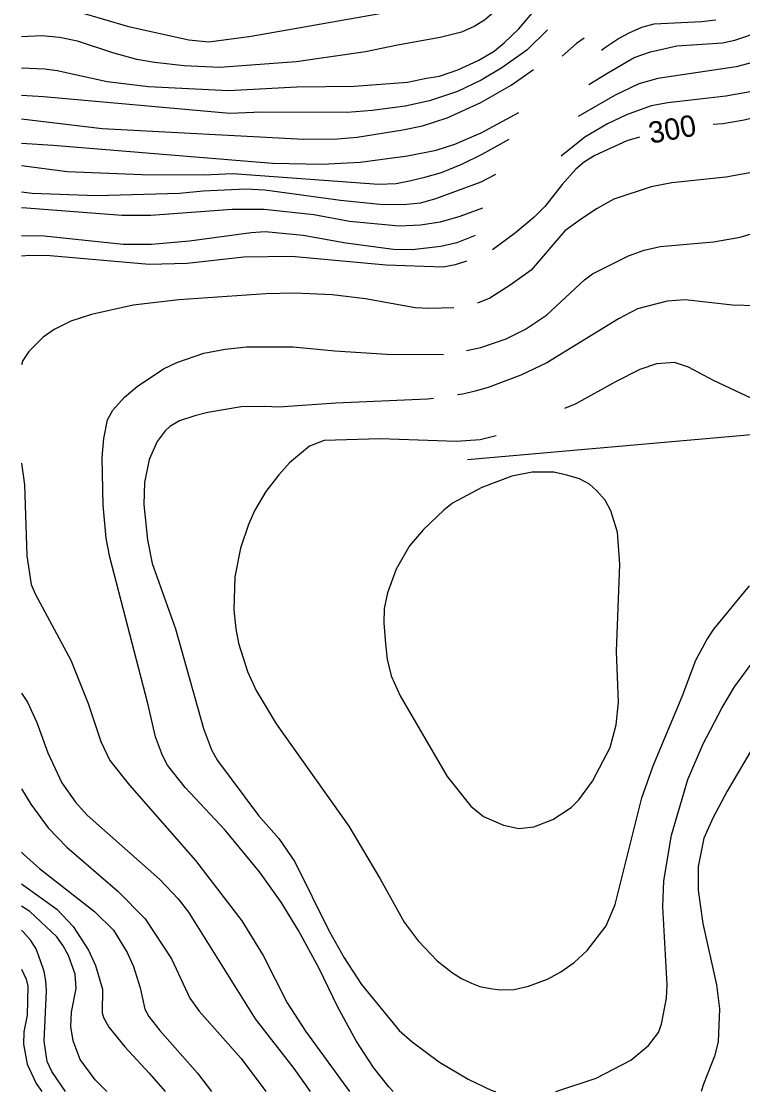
# Model space of a CAD drawing. Extents: x -555860 to -552701, y -1187050 to -1182291.
# Drawn here: x -555860 to -555523, y -1187050 to -1186550 of the extents above; entities that cross this region are included whole.
import ezdxf

# ---------------------------------------------------------------- set-up
doc = ezdxf.new("R2010")
doc.units = 0
for name, color, linetype in [('Level 28', 7, 'Continuous'), ('Level 40', 7, 'Continuous'), ('Level 41', 7, 'Continuous')]:
    doc.layers.add(name, color=color, linetype=linetype)

msp = doc.modelspace()

# ---------------------------------------------------------------- linework, layer by layer
at = {"layer": 'Level 28'}
msp.add_lwpolyline([(-555508.02, -1186742.24), (-555651.46, -1186754.81)], dxfattribs=at)
at = {"layer": 'Level 40'}
for points in [[(-555860.13, -1186544.05), (-555858.07, -1186543.84), (-555842.82, -1186543.42), (-555833.39, -1186545.22), (-555810.09, -1186552.02), (-555781.81, -1186558.26), (-555772.38, -1186559.23), (-555752.69, -1186556.59), (-555687.21, -1186544.99), (-555675.87, -1186541.34), (-555659.23, -1186538.01), (-555653.69, -1186536.21), (-555643.98, -1186531.22), (-555635.66, -1186525.4), (-555632.06, -1186521.65), (-555608.21, -1186491.01), (-555601.55, -1186483.94), (-555594.19, -1186479.33), (-555587.69, -1186476.59), (-555567.15, -1186470.24)], [(-555430.17, -1186544.81), (-555482.03, -1186578.36), (-555506.99, -1186591.4), (-555511.98, -1186593.34), (-555521.96, -1186595.83), (-555531.95, -1186597.5), (-555536.57, -1186597.92)], [(-555596.95, -1186557.53), (-555600.51, -1186559.99), (-555607.24, -1186565.88)], [(-555860.13, -1186606.69), (-555845.31, -1186607.62), (-555742.7, -1186615.94), (-555719.41, -1186616.49), (-555701.66, -1186615.52), (-555679.48, -1186612.61), (-555666.17, -1186609.84), (-555657.43, -1186607.06), (-555645.09, -1186601.8), (-555627.48, -1186592.23)], [(-555571, -1186603.8), (-555576.87, -1186605.54), (-555591.85, -1186612.33), (-555596.7, -1186615.38), (-555600.72, -1186618.85), (-555607.24, -1186625.92), (-555615.14, -1186636.04), (-555620.27, -1186641.31), (-555629.01, -1186648.52), (-555639.79, -1186656.58)], [(-555651.92, -1186661.77), (-555657.29, -1186663.61), (-555662.84, -1186664.61), (-555689.46, -1186663.78), (-555733.83, -1186659.62), (-555756.02, -1186660.03), (-555782.64, -1186662.94), (-555800.39, -1186663.36), (-555846.7, -1186659.34), (-555856.13, -1186659.2), (-555860.13, -1186659.55)], [(-555689.88, -1186840.84), (-555688.96, -1186848.14), (-555687.1, -1186855.82), (-555682.94, -1186865.24), (-555660.9, -1186902.96), (-555649.94, -1186916.82), (-555643.98, -1186921.68), (-555634.55, -1186925.7), (-555627.39, -1186927.4), (-555620.49, -1186926.6), (-555611.54, -1186923.06), (-555602.94, -1186917.52), (-555599.33, -1186913.91), (-555592.95, -1186905.18), (-555584.64, -1186889.37), (-555581.86, -1186878.83), (-555580.75, -1186868.29), (-555581.72, -1186844.45), (-555580.2, -1186803.68), (-555581.31, -1186788.71), (-555584.36, -1186778.72), (-555587.13, -1186773.73), (-555590.88, -1186769.29), (-555594.34, -1186766.24), (-555599.1, -1186763.74), (-555604.98, -1186762.04), (-555611.09, -1186760.64), (-555621.24, -1186760.56), (-555630.67, -1186762.5), (-555644.81, -1186767.77), (-555658.4, -1186775.12), (-555662.56, -1186778.31), (-555671.99, -1186787.46), (-555678.65, -1186795.08), (-555684.88, -1186805.9), (-555688.91, -1186816.99), (-555690.45, -1186824.38), (-555690.57, -1186831.13), (-555689.88, -1186840.84)], [(-555860.13, -1186864.04), (-555857.23, -1186868.29), (-555852.94, -1186877.72), (-555847.81, -1186891.87), (-555841.15, -1186906.01), (-555834.77, -1186915.02), (-555829.36, -1186921.12), (-555795.39, -1186951.21), (-555786.8, -1186960.22), (-555781.95, -1186966.46), (-555750.75, -1187016.38), (-555732.72, -1187039.68), (-555725.07, -1187050.46)], [(-555839.57, -1187050.46), (-555845.86, -1187041.06), (-555848.08, -1187036.35), (-555849.47, -1187026.92), (-555848.36, -1187003.35), (-555848.64, -1186998.63), (-555849.54, -1186994.31), (-555851.13, -1186989.2), (-555853.25, -1186983.66), (-555855.71, -1186979.77), (-555859.39, -1186975.5), (-555860.13, -1186974.92)]]:
    msp.add_lwpolyline(points, dxfattribs=at)
at = {"layer": 'Level 41'}
for points in [[(-555594.65, -1186579.2), (-555585.5, -1186573.52), (-555573.54, -1186566.58), (-555565.78, -1186563.8), (-555553.58, -1186561.03), (-555532.22, -1186559.64), (-555526.39, -1186558.42), (-555520.3, -1186556.32), (-555514.75, -1186553.82), (-555505.88, -1186547.58), (-555499.64, -1186542.03), (-555478.15, -1186520.68), (-555466.08, -1186511.67), (-555457.35, -1186508.06), (-555451.25, -1186506.4), (-555430.73, -1186503.76), (-555422.94, -1186502.1), (-555416.58, -1186500.16), (-555410.76, -1186497.25), (-555397.17, -1186487.68), (-555379.15, -1186472.29), (-555345.18, -1186434.71)], [(-555573.34, -1186489.11), (-555582.97, -1186491.43), (-555591.29, -1186494.75), (-555595.43, -1186497.15), (-555599.61, -1186499.88), (-555607.24, -1186507.51), (-555632.75, -1186539.82), (-555643.57, -1186549.11), (-555648.38, -1186551.98), (-555654.24, -1186554.65), (-555664.22, -1186557.15), (-555684.19, -1186560.75), (-555699.17, -1186563.94), (-555731.61, -1186568.52), (-555767.39, -1186571.15), (-555784.03, -1186570.46), (-555797.89, -1186568.93), (-555806.21, -1186567.41), (-555817.3, -1186564.36), (-555833.94, -1186558.81), (-555842.26, -1186557.15), (-555850.58, -1186556.45), (-555860.13, -1186556.79)], [(-555860.13, -1186571.37), (-555849.19, -1186571.84), (-555843.37, -1186572.68), (-555820.07, -1186577.81), (-555800.66, -1186580.03), (-555763.23, -1186581.97), (-555731.33, -1186580.3), (-555704.44, -1186579.89), (-555679.48, -1186578.09), (-555670.66, -1186576.24), (-555664.5, -1186575.31), (-555656.05, -1186572.28), (-555646.48, -1186567.96), (-555638.97, -1186563.62), (-555634.28, -1186559.64), (-555627.48, -1186553.13), (-555621.93, -1186546.75), (-555600.17, -1186517.63), (-555596.01, -1186513.89), (-555589.63, -1186509.73), (-555578.91, -1186504.86)], [(-555462.62, -1186527.34), (-555492.98, -1186554.38), (-555508.38, -1186564.64), (-555512.78, -1186566.84), (-555518.08, -1186568.8), (-555525.84, -1186570.88), (-555562.45, -1186576.42), (-555571.32, -1186578.92), (-555582.42, -1186584.19), (-555599.64, -1186594.08)], [(-555376.1, -1186543.14), (-555395.09, -1186555.76), (-555421.85, -1186571.29), (-555447.92, -1186584.88), (-555469.97, -1186600.41), (-555480.92, -1186607.34), (-555489.79, -1186612.19), (-555501.44, -1186616.22), (-555515.03, -1186619.68), (-555530.56, -1186622.46), (-555555.8, -1186625.23), (-555565.5, -1186627.03), (-555582.97, -1186632.85), (-555590.74, -1186637.15), (-555598.13, -1186642.08), (-555605.99, -1186647.69), (-555621.66, -1186665.99), (-555631.55, -1186673.02), (-555640.93, -1186679.17), (-555646.83, -1186681.53)], [(-555455.96, -1186541.76), (-555483.14, -1186565.61), (-555495.9, -1186574.76), (-555502.55, -1186578.22), (-555509.06, -1186580.45), (-555519.19, -1186582.66), (-555530.56, -1186584.6), (-555557.74, -1186587.79), (-555565.5, -1186589.18), (-555577.15, -1186593.34), (-555586, -1186597.53), (-555596.56, -1186603.74), (-555607.65, -1186612.68)], [(-555614.1, -1186553.61), (-555623.62, -1186563.12), (-555635.38, -1186571.43), (-555645.09, -1186577.11), (-555656.18, -1186582.38), (-555669.17, -1186586.88), (-555680.56, -1186589.36), (-555696.12, -1186591.4), (-555707.76, -1186592.23), (-555747.7, -1186592.09), (-555762.67, -1186592.78), (-555849.75, -1186584.88), (-555860.13, -1186584.26)], [(-555588.7, -1186563.04), (-555587.41, -1186562), (-555580.89, -1186557.56), (-555575.85, -1186554.96), (-555569.94, -1186552.3), (-555564.11, -1186550.77), (-555541.93, -1186549.66), (-555535.27, -1186548.83)], [(-555860.13, -1186595.17), (-555822.29, -1186599.72), (-555728.01, -1186604.71), (-555712.2, -1186604.57), (-555703.05, -1186603.74), (-555681.7, -1186600.41), (-555672.54, -1186598.47), (-555660.9, -1186594.72), (-555645.23, -1186587.65), (-555631.09, -1186579.47), (-555620.63, -1186572.07)], [(-555860.13, -1186617.08), (-555838.66, -1186619.82), (-555803.71, -1186621.21), (-555774.6, -1186621.49), (-555761.29, -1186620.79), (-555693.07, -1186625.78), (-555684.77, -1186625.5), (-555678.65, -1186624.26), (-555671.4, -1186622.53), (-555663.67, -1186620.38), (-555654.1, -1186616.49), (-555644.54, -1186611.78), (-555632, -1186604.71)], [(-555638.34, -1186621.31), (-555645.25, -1186624.93), (-555666.44, -1186632.72), (-555673.38, -1186634.65), (-555679.76, -1186635.35), (-555690.85, -1186635.49), (-555710.81, -1186633.41), (-555746.31, -1186628.56), (-555755.18, -1186628.14), (-555775.15, -1186629.11), (-555786.24, -1186630.22), (-555825.07, -1186631.19), (-555855.02, -1186630.22), (-555860.13, -1186629.54)], [(-555644.38, -1186637.08), (-555655.07, -1186640.9), (-555664.22, -1186643.56), (-555673.38, -1186644.92), (-555683.36, -1186645.47), (-555706.65, -1186643.25), (-555723.29, -1186640.2), (-555746.59, -1186637.71), (-555761.56, -1186637.71), (-555799.55, -1186640.48), (-555813.14, -1186640.48), (-555857.79, -1186637.01), (-555860.13, -1186636.9)], [(-555647.81, -1186649.86), (-555656.47, -1186653.26), (-555663.95, -1186655.04), (-555677.26, -1186656.57), (-555686.13, -1186656.43), (-555708.32, -1186653.38), (-555728.29, -1186649.77), (-555746.03, -1186648.11), (-555752.69, -1186648.52), (-555781.53, -1186652.54), (-555799.28, -1186654.07), (-555812.59, -1186654.07), (-555849.47, -1186650.19), (-555860.13, -1186650.01)], [(-555651.85, -1186703.66), (-555645.16, -1186702.22), (-555633.44, -1186698.16), (-555624.29, -1186693.59), (-555614.45, -1186687.07), (-555596.7, -1186670.57), (-555592.95, -1186667.8), (-555576.18, -1186659.34), (-555568.83, -1186656.7), (-555561.34, -1186654.9), (-555536.38, -1186652.82), (-555523.9, -1186650.6), (-555508.93, -1186646.03)], [(-555657.87, -1186683.62), (-555669.49, -1186684.06), (-555675.87, -1186683.6), (-555699.17, -1186679.44), (-555714.7, -1186677.64), (-555732.17, -1186676.81), (-555745.76, -1186677.09), (-555786.52, -1186679.86), (-555807.87, -1186682.49), (-555827.29, -1186686.79), (-555836.99, -1186689.98), (-555844.76, -1186693.86), (-555849.89, -1186697.47), (-555856.68, -1186704.12), (-555859.45, -1186708.28), (-555860.13, -1186710.38)], [(-555516.42, -1186682.77), (-555527.51, -1186682.49), (-555549.69, -1186679.86), (-555558.01, -1186680.55), (-555571.88, -1186684.16), (-555580.75, -1186688.87), (-555614.31, -1186709.39), (-555626.51, -1186715.22), (-555641.76, -1186720.9), (-555647.87, -1186722.65), (-555653.69, -1186724.09), (-555656.15, -1186724.44)], [(-555686.25, -1187050.46), (-555688.21, -1187048.27), (-555695.42, -1187039.12), (-555703.46, -1187026.64), (-555712.34, -1187010.56), (-555720.8, -1186992.81), (-555730.5, -1186975.06), (-555738.55, -1186961.75), (-555748.81, -1186947.61), (-555764.89, -1186928.19), (-555783.47, -1186908.09), (-555791.79, -1186897.69), (-555794.15, -1186893.25), (-555797.47, -1186884.38), (-555800.94, -1186868.85), (-555818.83, -1186800.35), (-555820.49, -1186791.48), (-555821.88, -1186775.95), (-555822.29, -1186753.76), (-555821.6, -1186744.89), (-555819.8, -1186736.02), (-555817.3, -1186731.58), (-555811.89, -1186725.48), (-555805.93, -1186720.49), (-555793.73, -1186712.3), (-555787.35, -1186709.26), (-555774.87, -1186704.96), (-555764.89, -1186703.02), (-555754.91, -1186701.91), (-555733, -1186701.91), (-555713.59, -1186703.85), (-555689.18, -1186705.37), (-555662.72, -1186705.44)], [(-555513.09, -1186728.53), (-555536.38, -1186717.71), (-555548.03, -1186711.47), (-555554.69, -1186709.25), (-555563.01, -1186709.81), (-555570.77, -1186712.58), (-555582.28, -1186718.27), (-555600.72, -1186728.53), (-555606.05, -1186730.81)], [(-555667.37, -1186726.03), (-555670.15, -1186726.42), (-555713.03, -1186728.25), (-555739.65, -1186730.19), (-555746.31, -1186729.78), (-555757.4, -1186730.05), (-555772.93, -1186732.69), (-555779.02, -1186734.28), (-555786.24, -1186736.57), (-555790.68, -1186739.2), (-555792.9, -1186741.28), (-555796.64, -1186746.28), (-555800.39, -1186754.59), (-555802.6, -1186765.41), (-555802.88, -1186775.67), (-555801.22, -1186792.31), (-555799, -1186803.4), (-555788.05, -1186833.91), (-555775.01, -1186880.5), (-555771.13, -1186890.48), (-555768.36, -1186895.47), (-555749.22, -1186921.26), (-555739.65, -1186932.08), (-555732.17, -1186942.89), (-555716.22, -1186975.34), (-555709.15, -1186987.82), (-555700.97, -1187000.3), (-555683.36, -1187021.93), (-555677.4, -1187027.2), (-555664.5, -1187036.76), (-555651.19, -1187044.67), (-555640.1, -1187049.93), (-555638.42, -1187050.46)], [(-555638.02, -1186743.5), (-555645.49, -1186745.5), (-555656.79, -1186746.3), (-555692.36, -1186744.98), (-555718.46, -1186745.73), (-555725.37, -1186748.36), (-555734.66, -1186756.26), (-555739.66, -1186761.76), (-555745.76, -1186769.57), (-555750.89, -1186778.44), (-555753.94, -1186785.1), (-555757.68, -1186796.19), (-555760.31, -1186809.5), (-555760.73, -1186825.03), (-555759.9, -1186833.91), (-555758.65, -1186840.56), (-555754.35, -1186853.87), (-555750.33, -1186862.75), (-555740.9, -1186878.28), (-555706.93, -1186926.25), (-555692.09, -1186951.21), (-555681.14, -1186971.18), (-555674.49, -1186979.91), (-555665.61, -1186989.34), (-555658.54, -1186994.89), (-555654.28, -1186997.52), (-555649.53, -1186999.74), (-555645.62, -1187001.24), (-555640.65, -1187002.24), (-555636.22, -1187002.79), (-555629.56, -1187002.65), (-555622.91, -1187001.13), (-555614.03, -1186997.8), (-555607.79, -1186994.47), (-555601.55, -1186990.04), (-555595.45, -1186984.49), (-555586.58, -1186972.84), (-555582.42, -1186962.86), (-555569.94, -1186912.94), (-555564.67, -1186897.97), (-555551.08, -1186865.52), (-555544.7, -1186848.61), (-555539.57, -1186839.04), (-555536.24, -1186834.05), (-555519.47, -1186813.8)], [(-555860.13, -1186756.43), (-555858.76, -1186766.52), (-555857.65, -1186799.8), (-555855.57, -1186813.11), (-555853.77, -1186817.55), (-555836.99, -1186848.61), (-555828.95, -1186868.85), (-555822.99, -1186886.6), (-555818.69, -1186895.47), (-555809.54, -1186906.98), (-555778.62, -1186942.34), (-555756.99, -1186970.62), (-555747, -1186986.71), (-555735.77, -1187008.89), (-555727.31, -1187022.2), (-555706.58, -1187050.46)], [(-555610.2, -1187050.46), (-555591.29, -1187044.11), (-555575.07, -1187035.79), (-555566.75, -1187028.86), (-555562.17, -1187022.76), (-555560.65, -1187018.88), (-555558.43, -1187006.68), (-555558.01, -1187000.57), (-555560.09, -1186963.97), (-555559.54, -1186951.77), (-555556.07, -1186930.41), (-555548.45, -1186904.35), (-555541.24, -1186887.71), (-555532.5, -1186871.07), (-555526.54, -1186861.08), (-555516.97, -1186848.05)], [(-555519.05, -1186891.31), (-555530.01, -1186909.89), (-555536.52, -1186922.23), (-555540.82, -1186931.8), (-555543.59, -1186945.11), (-555543.59, -1186956.2), (-555541.38, -1186971.73), (-555535, -1187000.57), (-555533.61, -1187011.67), (-555534.17, -1187027.2), (-555535.97, -1187033.85), (-555541.1, -1187047.02), (-555542.09, -1187050.46)], [(-555860.13, -1186908.78), (-555855.71, -1186915.99), (-555847.67, -1186927.09), (-555838.93, -1186936.1), (-555815.08, -1186956.62), (-555802.19, -1186969.65), (-555789.85, -1186988.37), (-555781.39, -1187006.68), (-555776.95, -1187012.78), (-555757.26, -1187034.96), (-555745.8, -1187050.46)], [(-555860.13, -1186938.41), (-555859.04, -1186939.56), (-555851.69, -1186946.08), (-555825.9, -1186966.19), (-555817.03, -1186974.92), (-555810.65, -1186985.32), (-555807.73, -1186991.98), (-555804.55, -1187001.96), (-555802.33, -1187011.94), (-555800.53, -1187015.27), (-555795.39, -1187021.93), (-555777.79, -1187041.89), (-555771.23, -1187050.46)], [(-555860.13, -1186953.17), (-555843.51, -1186965.08), (-555835.88, -1186973.12), (-555828.67, -1186984.21), (-555825.48, -1186991.42), (-555822.16, -1187002.51), (-555822.29, -1187013.61), (-555821.74, -1187015.82), (-555819.24, -1187020.26), (-555811.76, -1187029.55), (-555800.39, -1187041.76), (-555792.95, -1187050.46)], [(-555820.13, -1187050.46), (-555825.62, -1187044.94), (-555832.69, -1187035.51), (-555835.88, -1187026.64), (-555836.99, -1187019.99), (-555836.71, -1187013.33), (-555834.5, -1187002.24), (-555835.05, -1186995.58), (-555838.1, -1186986.71), (-555840.63, -1186982.18), (-555843.51, -1186977.97), (-555856.13, -1186966.19), (-555860.13, -1186963.7)], [(-555860.13, -1186993.21), (-555857.93, -1186997.8), (-555857.1, -1187001.13), (-555857.51, -1187014.72), (-555859.04, -1187022.48), (-555859.18, -1187028.3), (-555857.51, -1187037.59), (-555853.21, -1187046.61), (-555850.52, -1187050.46)]]:
    msp.add_lwpolyline(points, dxfattribs=at)

# ---------------------------------------------------------------- texts
at = {"layer": 'Level 40'}
msp.add_text('300', height=10, rotation=10.2377, dxfattribs=at).set_placement((-555565.78, -1186606.89))

doc.saveas('drawing.dxf')
